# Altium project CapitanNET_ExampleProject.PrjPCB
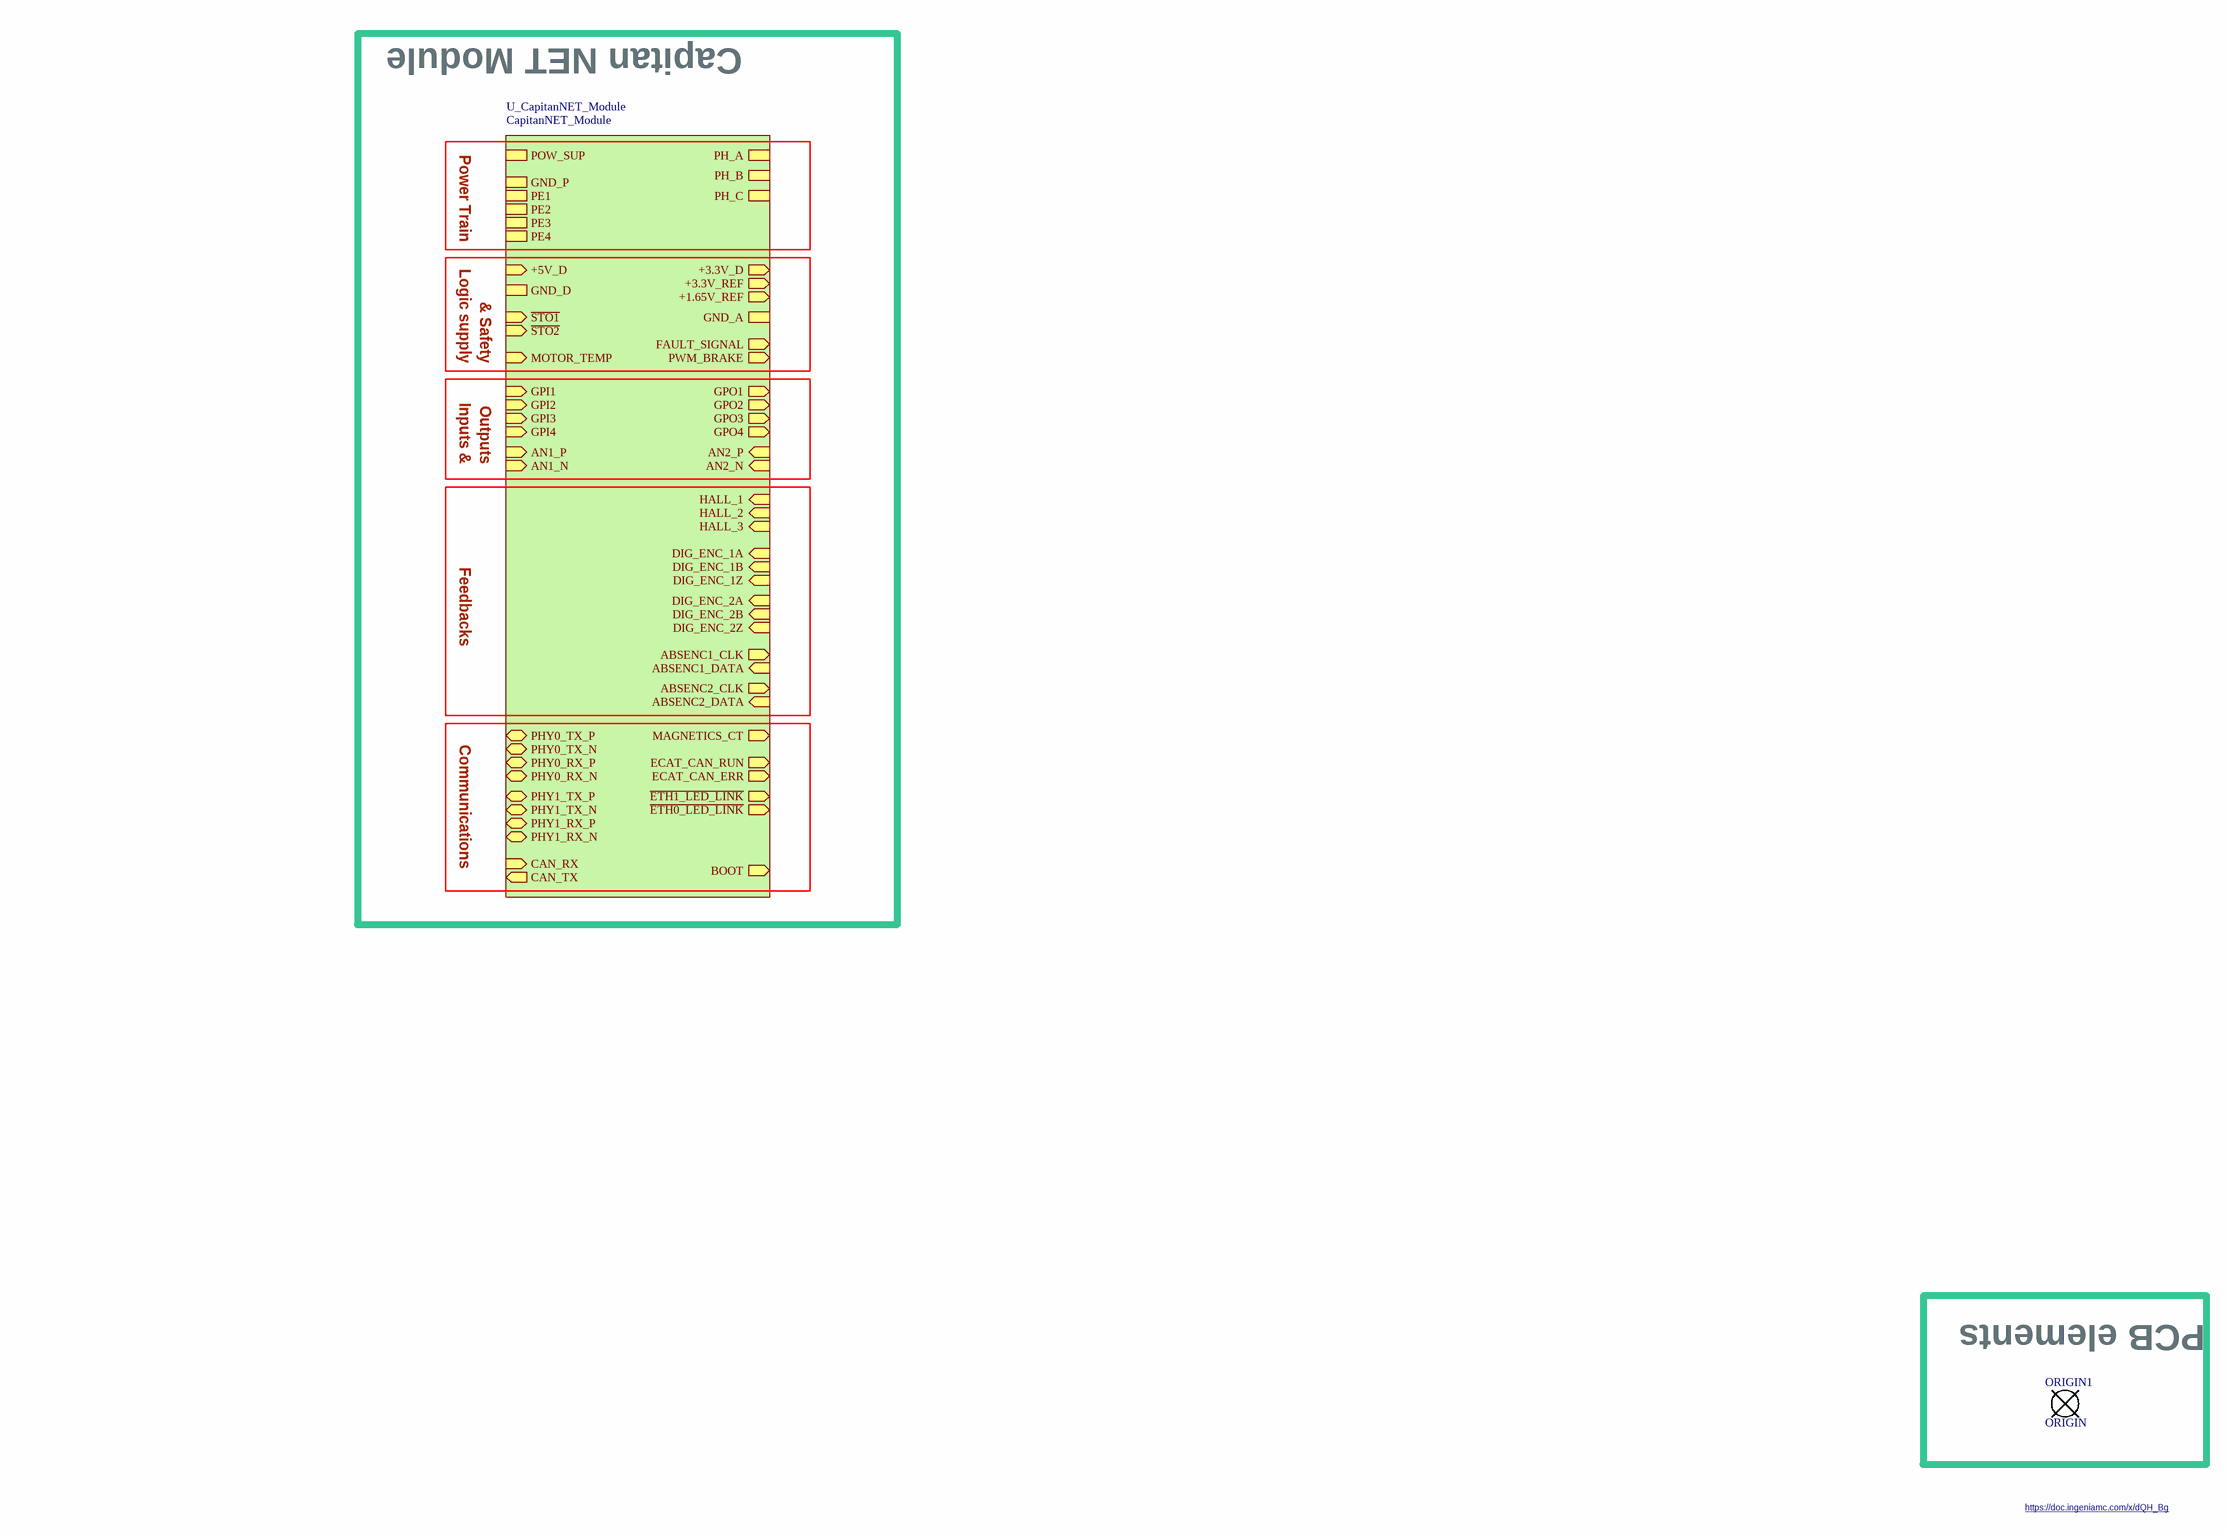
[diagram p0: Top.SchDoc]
1 sheet, 1 parts. Net scope: hierarchical (ports join the sheet entries above them; power ports are global).
Board file: CapitanNET_ExampleProject.PcbDoc

## Sheet Top.SchDoc: ixxx
size A2; Documentation: https://doc.ingeniamc.com/x/dQH_Bg; Organization: Ingenia Motion Control; Address1: Carrer Avila, 124; Address2: 08018 Barcelona Spain; Address3: www.ingeniamc.com; Address4: www.ingeniamc.com

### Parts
ORIGIN1  ORIGIN  [ORIGIN]

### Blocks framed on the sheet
PCB elements: ORIGIN1

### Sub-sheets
U_CapitanNET_Module = CapitanNET_Module (file not in this document): AN1_P (in), AN1_N (in), DIG_ENC_1A (in), DIG_ENC_1B (in), DIG_ENC_1Z (in), DIG_ENC_2A (in), DIG_ENC_2B (in), DIG_ENC_2Z (in), ABSENC1_CLK (out), ABSENC1_DATA (in), MOTOR_TEMP (in), HALL_1 (in), HALL_2 (in), HALL_3 (in), +3.3V_D (out), GPO4 (out), +3.3V_REF (out), +5V_D (in), GPI2 (in), ABSENC2_DATA (in), GPO1 (out), GPO3 (out), ~{STO1} (in), PWM_BRAKE (out), CAN_TX (out), CAN_RX (in), ECAT_CAN_RUN (out), ~{ETH0_LED_LINK} (out), PHY0_TX_P (bidir), PHY0_TX_N (bidir), PHY0_RX_P (bidir), PHY0_RX_N (bidir), +1.65V_REF (out), GPI1 (in), GPI3 (in), ABSENC2_CLK (out), GPO2 (out), GPI4 (in), ~{STO2} (in), FAULT_SIGNAL (out), ECAT_CAN_ERR (out), ~{ETH1_LED_LINK} (out), PHY1_TX_P (bidir), PHY1_TX_N (bidir), PHY1_RX_P (bidir), PHY1_RX_N (bidir), GND_A, GND_D, PE1, PE2, PE3, PE4, POW_SUP, GND_P, PH_C, PH_B, PH_A, MAGNETICS_CT (out), BOOT (out), AN2_N (in), AN2_P (in)

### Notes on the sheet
- Capitan NET Module
- Power Train
- Logic supply
- & Safety
- Inputs &
- Outputs
- Feedbacks
- Communications
- https://doc.ingeniamc.com/x/dQH_Bg

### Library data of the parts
ORIGIN1 = ORIGIN: Origin of coordinate axes for pick and place; IsPreferred: True; IngeniaID: 1109; InternalStock: 0; TemperatureMaxC: 200; TemperatureMinC: -60; MTBF55h: 1E20

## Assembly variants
BASIC: all parts fitted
